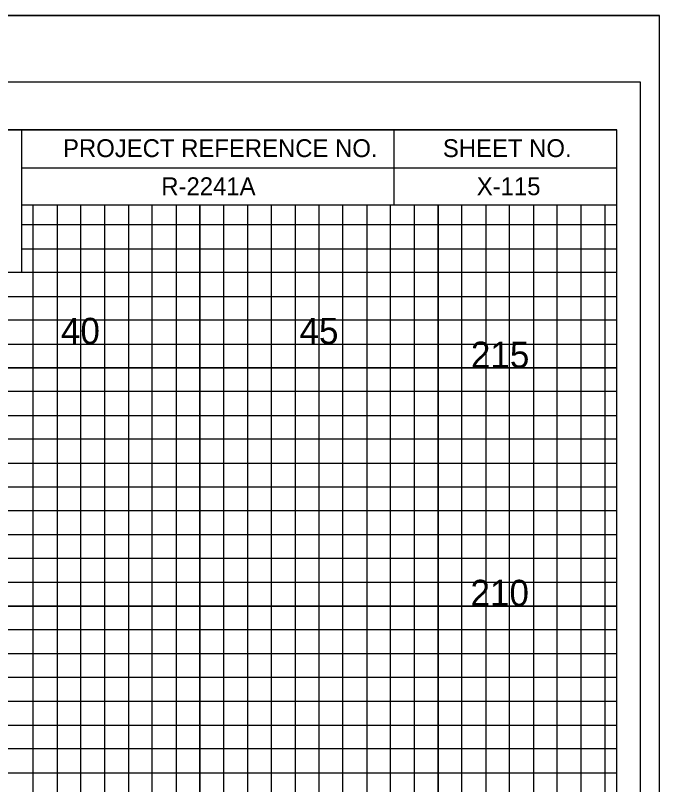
# Model space of a CAD drawing. Extents: x -4 to 103, y -2 to 492.
# Drawn here: x 89.88 to 103.4, y 334.55 to 350.7 of the extents above; entities that cross this region are included whole.
import ezdxf

# ---------------------------------------------------------------- set-up
doc = ezdxf.new("R2010")
doc.units = 0
for name, color, linetype in [('Exist XS Center Line Elevation Label', 7, 'Continuous'), ('Exist XS Ground Line', 7, 'Continuous'), ('Old_Level_10', 7, 'Continuous'), ('Old_Level_16', 7, 'Continuous'), ('Old_Level_3', 7, 'Continuous'), ('Old_Level_5', 7, 'Continuous'), ('Old_Level_8', 7, 'Continuous'), ('Prop Dimension', 7, 'Continuous'), ('Prop XS Finish Grade Earthwork', 7, 'Continuous'), ('Prop XS SE Text', 7, 'Continuous'), ('Prop XSC Text', 7, 'Continuous')]:
    doc.layers.add(name, color=color, linetype=linetype)

msp = doc.modelspace()

# ---------------------------------------------------------------- linework, layer by layer
at = {"layer": 'Old_Level_10'}
for p, q in [((91.25, 283.3), (91.25, 346.725)), ((93.75, 283.3), (93.75, 346.725)), ((96.25, 283.3), (96.25, 346.725)), ((98.75, 283.3), (98.75, 346.725)), ((101.25, 283.3), (101.25, 346.725)), ((90, 345.8), (102.5, 345.8)), ((0, 343.3), (102.5, 343.3)), ((0, 340.8), (102.5, 340.8)), ((0, 338.3), (102.5, 338.3)), ((0, 335.8), (102.5, 335.8))]:
    msp.add_line(p, q, dxfattribs=at)
at = {"layer": 'Old_Level_3'}
msp.add_line((-3.5, 350.7), (103.4, 350.7), dxfattribs=at)
at = {"layer": 'Old_Level_5'}
msp.add_lwpolyline([(103.4, 350.7), (-3.5, 350.7), (-3.5, 280.875), (103.4, 280.875)], close=True, dxfattribs=at)
at = {"layer": 'Old_Level_8'}
for points in [[(91.25, 283.3), (91.25, 346.725), (93.75, 346.725), (93.75, 283.3)], [(96.25, 283.3), (96.25, 346.725), (98.75, 346.725), (98.75, 283.3)], [(101.25, 283.3), (101.25, 346.725)], [(90, 345.8), (102.5, 345.8)], [(0, 340.8), (102.5, 340.8), (102.5, 343.3), (0, 343.3)], [(0, 335.8), (102.5, 335.8), (102.5, 338.3), (0, 338.3)]]:
    msp.add_lwpolyline(points, dxfattribs=at)
at = {"layer": 'Prop Dimension'}
for points in [[(90.25, 283.3), (90.25, 346.725), (90.75, 346.725), (90.75, 283.3)], [(91.75, 283.3), (91.75, 346.725), (92.25, 346.725), (92.25, 283.3)], [(92.75, 283.3), (92.75, 346.725), (93.25, 346.725), (93.25, 283.3)], [(94.25, 283.3), (94.25, 346.725), (94.75, 346.725), (94.75, 283.3)], [(95.25, 283.3), (95.25, 346.725), (95.75, 346.725), (95.75, 283.3)], [(96.75, 283.3), (96.75, 346.725), (97.25, 346.725), (97.25, 283.3)], [(97.75, 283.3), (97.75, 346.725), (98.25, 346.725), (98.25, 283.3)], [(99.25, 283.3), (99.25, 346.725), (99.75, 346.725), (99.75, 283.3)], [(100.25, 283.3), (100.25, 346.725)], [(100.25, 346.725), (100.75, 346.725), (100.75, 283.3), (101.75, 283.3), (101.75, 346.725), (102.25, 346.725), (102.25, 283.3)], [(102.5, 345.3), (102.5, 346.3), (90, 346.3)], [(0, 344.8), (102.5, 344.8), (102.5, 345.3), (0, 345.3)], [(0, 343.8), (102.5, 343.8), (102.5, 344.3), (0, 344.3)], [(0, 342.3), (102.5, 342.3), (102.5, 342.8), (0, 342.8)], [(0, 341.3), (102.5, 341.3), (102.5, 341.8), (0, 341.8)], [(0, 339.8), (102.5, 339.8), (102.5, 340.3), (0, 340.3)], [(0, 338.8), (102.5, 338.8), (102.5, 339.3), (0, 339.3)], [(0, 337.3), (102.5, 337.3), (102.5, 337.8), (0, 337.8)], [(0, 336.3), (102.5, 336.3), (102.5, 336.8), (0, 336.8)], [(0, 334.8), (102.5, 334.8), (102.5, 335.3), (0, 335.3)]]:
    msp.add_lwpolyline(points, dxfattribs=at)
at = {"layer": 'Prop XS SE Text'}
msp.add_lwpolyline([(103, 349.3), (-2.8, 349.3), (-2.8, 282.3), (103, 282.3)], close=True, dxfattribs=at)
at = {"layer": 'Prop XSC Text'}
for p, q in [((90, 348.3), (102.5, 348.3)), ((90, 348.3), (102.5, 348.3)), ((97.825, 346.725), (97.825, 348.3)), ((101.875, 348.3), (101.875, 348.3)), ((102.5, 348.3), (102.5, 348.3)), ((102.5, 346.725), (102.5, 348.3)), ((102.5, 348.3), (102.5, 348.3)), ((102.5, 348.3), (102.5, 348.3)), ((102.5, 346.725), (102.5, 348.3)), ((90, 347.5), (102.5, 347.5)), ((90, 346.725), (102.5, 346.725)), ((99.4, 346.725), (99.4, 346.725)), ((99.4, 346.725), (99.4, 346.725))]:
    msp.add_line(p, q, dxfattribs=at)
for points in [[(102.5, 348.3), (0, 348.3), (0, 283.3), (102.5, 283.3)], [(83.75, 348.3), (90, 348.3), (90, 345.3), (83.75, 345.3)]]:
    msp.add_lwpolyline(points, close=True, dxfattribs=at)

# ---------------------------------------------------------------- texts
at = {"layer": 'Exist XS Center Line Elevation Label'}
msp.add_text('R-2241A', height=0.375, dxfattribs=at).set_placement((92.9378, 346.925))
at = {"layer": 'Exist XS Ground Line'}
msp.add_text('X-115', height=0.375, dxfattribs=at).set_placement((99.5613, 346.925))
at = {"layer": 'Old_Level_16'}
for s, p in [('40', (90.8313, 343.8)), ('45', (95.8399, 343.8))]:
    msp.add_text(s, height=0.55, dxfattribs=at).set_placement(p)
at = {"layer": 'Prop XS Finish Grade Earthwork'}
for s, p in [('215', (99.4383, 343.3)), ('210', (99.4296, 338.3))]:
    msp.add_text(s, height=0.55, dxfattribs=at).set_placement(p)
at = {"layer": 'Prop XSC Text'}
for s, p in [('PROJECT REFERENCE NO.', (90.875, 347.725)), ('SHEET NO.', (98.85, 347.725))]:
    msp.add_text(s, height=0.375, dxfattribs=at).set_placement(p)

doc.saveas('drawing.dxf')
